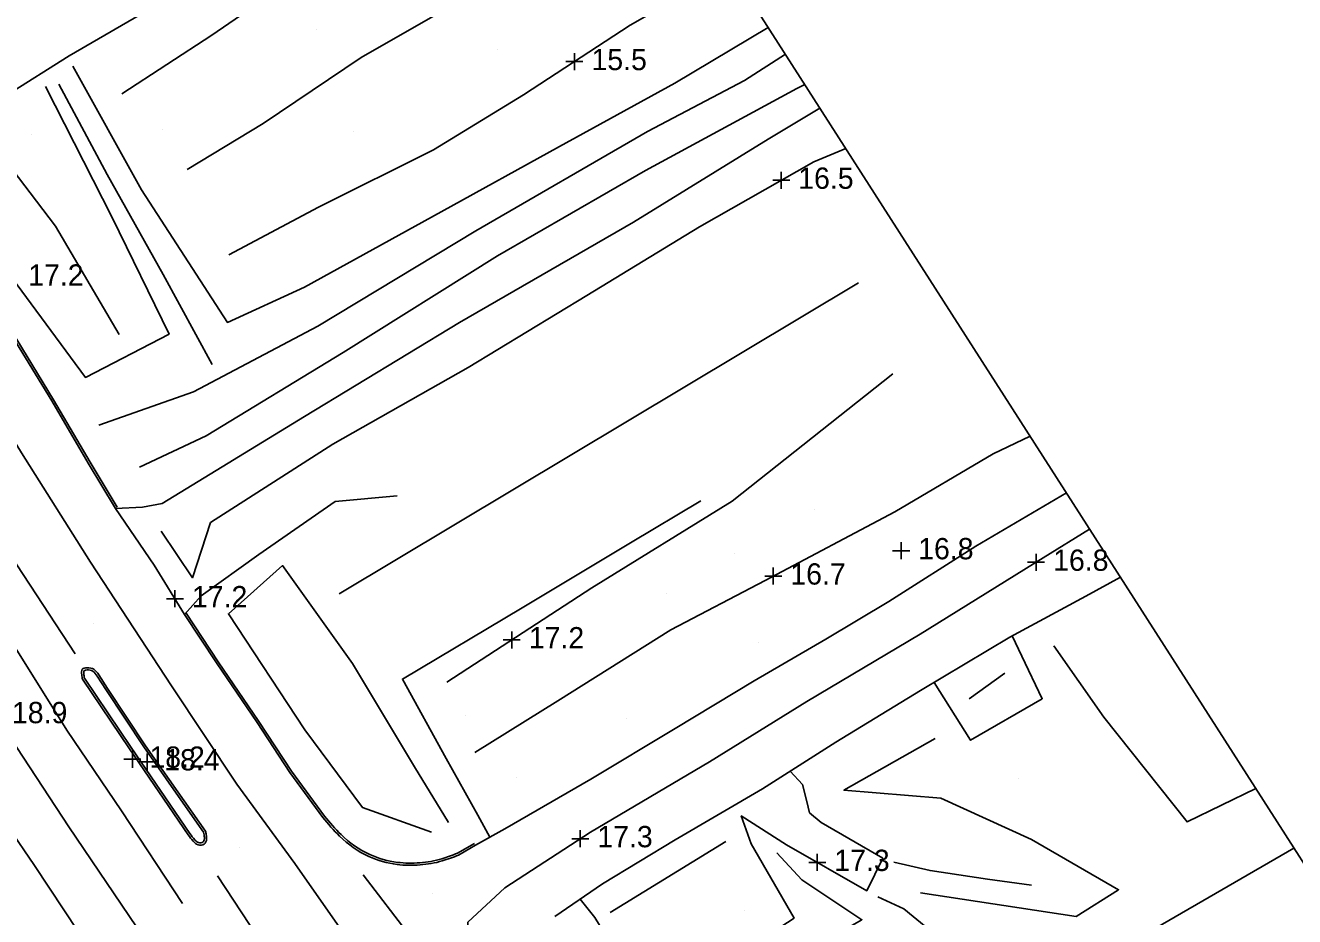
# Model space of a CAD drawing. Extents: x 2316231 to 2323598, y 363169 to 371906.
# Drawn here: x 2318218.6 to 2318516.9, y 368285.8 to 368495.1 of the extents above; entities that cross this region are included whole.
import ezdxf

# ---------------------------------------------------------------- set-up
doc = ezdxf.new("R2010")
doc.units = 0
for name, color, linetype in [('RD_DTM_BkLn1', 7, 'Continuous'), ('RD_DTM_Spot', 7, 'Continuous'), ('RD_DTM_TinHull', 7, 'Continuous'), ('RD_DTM_Void', 7, 'Continuous'), ('RD_EX_Road', 7, 'Continuous')]:
    doc.layers.add(name, color=color, linetype=linetype)

msp = doc.modelspace()

# ---------------------------------------------------------------- linework, layer by layer
at = {"layer": 'RD_DTM_BkLn1'}
for p, q in [((2318292.326, 368361.63), (2318414.386, 368434.679)), ((2318448.797, 368342.996), (2318440.431, 368336.936)), ((2318356.079, 368286.792), (2318383.218, 368303.461))]:
    msp.add_line(p, q, dxfattribs=at)
for points in [[(2318241.243, 368479.032), (2318262.406, 368492.85), (2318285.367, 368508.686), (2318304.64, 368522.026), (2318332.64, 368536.695), (2318356.237, 368552.259)], [(2318256.621, 368461.284), (2318274.492, 368472.064), (2318297.56, 368487.61), (2318319.864, 368500.378), (2318347.555, 368516.529), (2318363.452, 368526.904), (2318369.907, 368530.939)], [(2318108.909, 368511.719), (2318119.482, 368492.765), (2318128.577, 368474.561), (2318137.782, 368457.548), (2318146.113, 368442.318), (2318156.88, 368423.953), (2318169.071, 368401.915), (2318184.84, 368375.946), (2318201.019, 368350.59), (2318211.871, 368332.526), (2318228.82, 368306.879), (2318246.55, 368280.761), (2318262.976, 368258.004), (2318282.016, 368231.101), (2318302.091, 368204.027), (2318315.434, 368185.909), (2318329.38, 368168.609), (2318343.565, 368150.201), (2318359.6, 368130.104), (2318375.72, 368110.741), (2318392.524, 368090.559), (2318408.321, 368071.979), (2318426.423, 368050.577)], [(2318266.409, 368441.273), (2318287.531, 368452.443), (2318314.53, 368465.923), (2318335.667, 368478.826), (2318360.771, 368495.15), (2318380.593, 368506.504), (2318384.133, 368508.752)], [(2318144.884, 368496.886), (2318156.518, 368473.032), (2318176.299, 368438.22), (2318198.994, 368398.492), (2318216.607, 368368.391), (2318230.329, 368347.481)], [(2318235.874, 368401.228), (2318258.107, 368409.086), (2318287.361, 368424.511), (2318324.501, 368446.862), (2318364.808, 368470.181), (2318387.604, 368482.19), (2318397.221, 368488.338)], [(2318107.859, 368482.862), (2318119.111, 368460.886), (2318130.428, 368440.788), (2318140.355, 368423.568), (2318153.126, 368402.636), (2318161.797, 368388.669), (2318168.932, 368377.064), (2318173.297, 368370.002), (2318182.582, 368355.913), (2318195.547, 368335.883), (2318208.297, 368315.962), (2318220.737, 368297.799), (2318234.567, 368276.936), (2318251.642, 368253.84), (2318264.372, 368235.965), (2318274.076, 368221.201), (2318287.649, 368203.986)], [(2318226.469, 368481.291), (2318237.82, 368460.085), (2318250.983, 368436.637), (2318262.49, 368415.503)], [(2318245.408, 368391.387), (2318261.093, 368398.693), (2318293.269, 368418.288), (2318329.591, 368441.026), (2318364.379, 368461.036), (2318399.899, 368480.31), (2318401.763, 368481.254)], [(2318250.526, 368376.332), (2318257.855, 368365.388), (2318262.108, 368378.353), (2318290.887, 368396.739), (2318322.662, 368414.757), (2318350.535, 368431.665), (2318377.059, 368447.842), (2318403.893, 368463.092), (2318411.419, 368466.194)], [(2318212.426, 368465.291), (2318225.687, 368448.005), (2318240.674, 368422.519)], [(2318187.577, 368444.658), (2318200.539, 368422.787), (2318217.711, 368394.708), (2318233.95, 368369.075), (2318252.986, 368340.03), (2318268.291, 368316.866), (2318281.97, 368298.278)], [(2318317.686, 368340.875), (2318351.745, 368363.041), (2318384.74, 368383.416), (2318422.51, 368413.312)], [(2318454.745, 368398.621), (2318446.045, 368394.486), (2318422.981, 368380.913), (2318392.474, 368364.769), (2318370.317, 368353.18), (2318343.768, 368336.498), (2318324.257, 368324.313)], [(2318297.959, 368295.572), (2318309.071, 368281.178), (2318322.694, 368264.613), (2318322.618, 368284.494), (2318331.288, 368292.586), (2318351.427, 368305.636), (2318379.431, 368322.147), (2318402.292, 368336.322), (2318428.936, 368352.161), (2318457.822, 368370.054), (2318468.711, 368376.84)], [(2318202.506, 368370.167), (2318216.755, 368348.148), (2318228.352, 368329.602), (2318241.236, 368310.667), (2318255.534, 368288.889)], [(2318318.035, 368307.899), (2318310.025, 368320.987), (2318295.504, 368345.268), (2318279.055, 368368.254), (2318266.333, 368356.922), (2318284.302, 368329.648), (2318297.813, 368311.41), (2318314.059, 368305.598)], [(2318460.316, 368349.373), (2318472.109, 368332.619), (2318491.636, 368308.037), (2318507.777, 368315.911)], [(2318428.959, 368291.386), (2318465.593, 368285.83), (2318475.523, 368292.115), (2318455.054, 368303.893), (2318433.761, 368313.58), (2318410.972, 368315.471), (2318432.42, 368327.663)], [(2318381.462, 368210.665), (2318413.592, 368231.342), (2318459.794, 368259.366), (2318484.397, 368283.19), (2318516.76, 368301.901)], [(2318370.12, 368208.102), (2318361.883, 368216.677), (2318351.888, 368230.515), (2318341.025, 368248.819), (2318335.886, 368259.854), (2318337.484, 368269.514), (2318347.381, 368277.279), (2318353.938, 368270.694), (2318358.302, 368257.843), (2318366.967, 368252.024), (2318371.832, 368258.897), (2318402.489, 368277.809), (2318415.214, 368285.05), (2318401.105, 368294.407), (2318395.21, 368300.751)], [(2318281.97, 368298.278), (2318296.931, 368276.872), (2318312.406, 368254.345), (2318326.554, 368235.3)], [(2318263.744, 368295.382), (2318280.644, 368269.759), (2318298.904, 368243.592), (2318319.542, 368215.542), (2318335.838, 368193.639), (2318352.144, 368171.291), (2318368.187, 368149.558), (2318380.209, 368132.791)]]:
    msp.add_lwpolyline(points, dxfattribs=at)
at = {"layer": 'RD_DTM_Spot'}
for p, q in [((2318286.924, 368494.168), (2318286.924, 368494.168)), ((2318329.468, 368489.454), (2318329.468, 368489.454)), ((2318220.162, 368469.499), (2318220.162, 368469.499)), ((2318250.84, 368470.575), (2318250.84, 368470.575)), ((2318295.837, 368470.308), (2318295.837, 368470.308)), ((2318404.016, 368381.424), (2318404.016, 368381.424)), ((2318385.195, 368371.067), (2318385.195, 368371.067)), ((2318424.441, 368371.727), (2318424.441, 368371.727)), ((2318369.348, 368361.606), (2318369.348, 368361.606)), ((2318234.689, 368354.548), (2318234.689, 368354.548)), ((2318390.95, 368350.114), (2318390.95, 368350.114)), ((2318322.038, 368333.055), (2318322.038, 368333.055)), ((2318359.97, 368332.347), (2318359.97, 368332.347)), ((2318333.92, 368318.443), (2318333.92, 368318.443)), ((2318451.944, 368318.233), (2318451.944, 368318.233)), ((2318268.993, 368302.001), (2318268.993, 368302.001)), ((2318314.22, 368291.143), (2318314.22, 368291.143)), ((2318387.635, 368287.312), (2318387.635, 368287.312))]:
    msp.add_line(p, q, dxfattribs=at)
at = {"layer": 'RD_DTM_TinHull'}
msp.add_lwpolyline([(2319557.442, 369523.873), (2318254.179, 368711.432), (2318782.433, 367887.547), (2318500.627, 367718.473), (2317350.395, 369314.708)], dxfattribs=at)
at = {"layer": 'RD_DTM_Void'}
for p, q in [((2318347.656, 368484.622), (2318347.656, 368488.622)), ((2318345.656, 368486.622), (2318349.656, 368486.622)), ((2318396.249, 368456.748), (2318396.249, 368460.748)), ((2318394.249, 368458.748), (2318398.249, 368458.748)), ((2318424.441, 368369.727), (2318424.441, 368373.727)), ((2318422.441, 368371.727), (2318426.441, 368371.727)), ((2318456.16, 368367.024), (2318456.16, 368371.024)), ((2318394.396, 368363.786), (2318394.396, 368367.786)), ((2318454.16, 368369.024), (2318458.16, 368369.024)), ((2318392.396, 368365.786), (2318396.396, 368365.786)), ((2318253.756, 368358.442), (2318253.756, 368362.442)), ((2318251.756, 368360.442), (2318255.756, 368360.442)), ((2318332.934, 368348.799), (2318332.934, 368352.799)), ((2318330.934, 368350.799), (2318334.934, 368350.799)), ((2318241.766, 368322.756), (2318245.766, 368322.756)), ((2318243.766, 368320.756), (2318243.766, 368324.756)), ((2318247.242, 368320.135), (2318247.242, 368324.135)), ((2318245.242, 368322.135), (2318249.242, 368322.135)), ((2318349.037, 368302.088), (2318349.037, 368306.088)), ((2318347.037, 368304.088), (2318351.037, 368304.088)), ((2318404.726, 368296.51), (2318404.726, 368300.51)), ((2318402.726, 368298.51), (2318406.726, 368298.51))]:
    msp.add_line(p, q, dxfattribs=at)
at = {"layer": 'RD_EX_Road'}
for p, q in [((2318320.156, 368300.684), (2318324.18, 368302.984)), ((2318320.365, 368300.228), (2318324.428, 368302.55)), ((2318324.428, 368302.55), (2318324.498, 368302.59))]:
    msp.add_line(p, q, dxfattribs=at)
for points in [[(2318199.017, 368460.997), (2318201.397, 368468.577), (2318214.285, 368478.754), (2318228.939, 368488.001), (2318249.617, 368499.954), (2318238.572, 368523.145), (2318216.69, 368511.086), (2318196.538, 368502.826), (2318182.772, 368498.151), (2318173.223, 368495.644)], [(2318229.728, 368485.556), (2318245.863, 368456.493), (2318266.098, 368425.363), (2318284.216, 368433.676), (2318316.291, 368451.309), (2318344.149, 368466.652), (2318371.247, 368481.54), (2318393.191, 368494.624)], [(2318199.017, 368460.997), (2318210.643, 368442.249), (2318232.733, 368412.451), (2318252.372, 368422.613), (2318238.989, 368450.034), (2318223.375, 368480.816)], [(2318239.791, 368381.687), (2318246.097, 368381.974), (2318250.721, 368382.794), (2318284.198, 368403.288), (2318320.639, 368425.352), (2318361.5, 368448.923), (2318393.146, 368468.398), (2318405.319, 368475.709)], [(2318197.023, 368454.723), (2318204.754, 368440.541), (2318214.813, 368423.321), (2318224.827, 368406.944), (2318233.375, 368392.279), (2318239.791, 368381.687)], [(2318197.462, 368454.962), (2318205.189, 368440.787), (2318215.243, 368423.578), (2318225.256, 368407.201), (2318233.805, 368392.535), (2318240.218, 368381.946)], [(2318256.007, 368356.788), (2318259.892, 368361.136), (2318273.512, 368370.854), (2318291.447, 368383.331), (2318306.012, 368384.671)], [(2318327.762, 368304.419), (2318324.923, 368309.617), (2318317.467, 368322.944), (2318307.218, 368341.572), (2318335.391, 368358.311), (2318360.842, 368373.6), (2318377.363, 368383.48)], [(2318324.428, 368302.55), (2318331.258, 368306.378), (2318351.502, 368318.044), (2318371.361, 368329.987), (2318389.931, 368341.199), (2318406.741, 368350.934), (2318421.575, 368359.819), (2318441.99, 368372.82), (2318463.282, 368385.307)], [(2318256.007, 368356.788), (2318248.872, 368368.369), (2318239.791, 368381.687)], [(2318475.969, 368365.519), (2318467.839, 368361.066), (2318450.007, 368351.417), (2318428.955, 368338.911), (2318409.119, 368326.799), (2318391.825, 368315.837), (2318371.352, 368303.836), (2318354.216, 368293.463), (2318343.055, 368285.797)], [(2318256.007, 368356.788), (2318263.504, 368345.374), (2318273.089, 368331.357), (2318280.742, 368319.679), (2318288.529, 368309.095)], [(2318256.425, 368357.062), (2318263.919, 368345.653), (2318273.504, 368331.635), (2318281.152, 368319.964), (2318288.918, 368309.41)], [(2318450.559, 368351.716), (2318452.813, 368346.958), (2318457.605, 368336.971), (2318440.747, 368327.224), (2318432.16, 368340.815)], [(2318256.857, 368305.001), (2318243.061, 368325.237), (2318232.013, 368341.604)], [(2318257.259, 368305.298), (2318243.475, 368325.518), (2318232.491, 368341.789)], [(2318235.465, 368342.282), (2318237.486, 368339.104), (2318246.441, 368325.644)], [(2318235.866, 368342.583), (2318237.905, 368339.377), (2318246.853, 368325.927)], [(2318246.853, 368325.927), (2318254.448, 368315.115), (2318260.974, 368305.846)], [(2318246.441, 368325.644), (2318254.039, 368314.827), (2318260.498, 368305.654)], [(2318348.972, 368289.861), (2318352.43, 368285.572), (2318359.985, 368273.196), (2318365.585, 368264.206), (2318385.915, 368276.762), (2318399.257, 368285.434), (2318389.173, 368302.87), (2318386.853, 368309.446), (2318397.525, 368302.623), (2318416.348, 368291.871), (2318420.131, 368299.505), (2318405.612, 368307.937), (2318402.933, 368310.193), (2318402.265, 368312.842), (2318401.263, 368316.816), (2318398.365, 368319.983)], [(2318422.717, 368298.596), (2318431.257, 368296.592), (2318444.744, 368294.625), (2318455.054, 368293.146)], [(2318418.968, 368290.469), (2318425.088, 368287.616), (2318436.452, 368278.276), (2318444.095, 368273.084), (2318453.452, 368270.284), (2318460.301, 368265.467)]]:
    msp.add_lwpolyline(points, dxfattribs=at)
for points in [[(2318232.013, 368341.604), (2318231.871, 368342.579), (2318231.982, 368343.903), (2318233.078, 368344.25), (2318234.714, 368343.897), (2318235.866, 368342.583)], [(2318232.491, 368341.789), (2318232.374, 368342.595), (2318232.452, 368343.527), (2318233.102, 368343.733), (2318234.447, 368343.443), (2318235.465, 368342.282)], [(2318288.529, 368309.095), (2318292.455, 368304.682), (2318299.316, 368299.913), (2318305.979, 368298.045), (2318311.37, 368297.949), (2318316.583, 368298.877), (2318320.365, 368300.228)], [(2318288.918, 368309.41), (2318292.789, 368305.059), (2318299.532, 368300.372), (2318306.052, 368298.544), (2318311.331, 368298.45), (2318316.455, 368299.362), (2318320.156, 368300.684)], [(2318260.974, 368305.846), (2318261.093, 368305.075), (2318261.138, 368303.655), (2318260.342, 368302.658), (2318258.826, 368302.83), (2318258.045, 368303.518), (2318256.857, 368305.001)], [(2318260.498, 368305.654), (2318260.594, 368305.029), (2318260.632, 368303.823), (2318260.123, 368303.186), (2318259.038, 368303.309), (2318258.408, 368303.864), (2318257.259, 368305.298)]]:
    msp.add_spline(points, degree=3, dxfattribs=at)

# ---------------------------------------------------------------- texts
at = {"layer": 'RD_DTM_Void'}
for s, p in [('15.5', (2318351.656, 368484.622)), ('16.5', (2318400.249, 368456.748)), ('17.2', (2318219.279, 368433.995)), ('16.8', (2318428.441, 368369.727)), ('16.8', (2318460.16, 368367.024)), ('16.7', (2318398.396, 368363.786)), ('17.2', (2318257.756, 368358.442)), ('17.2', (2318336.934, 368348.799)), ('18.9', (2318215.452, 368331.223)), ('18.2', (2318247.766, 368320.756)), ('18.4', (2318251.242, 368320.135)), ('17.3', (2318353.037, 368302.088)), ('17.3', (2318408.726, 368296.51))]:
    msp.add_text(s, height=5, dxfattribs=at).set_placement(p)

doc.saveas('drawing.dxf')
